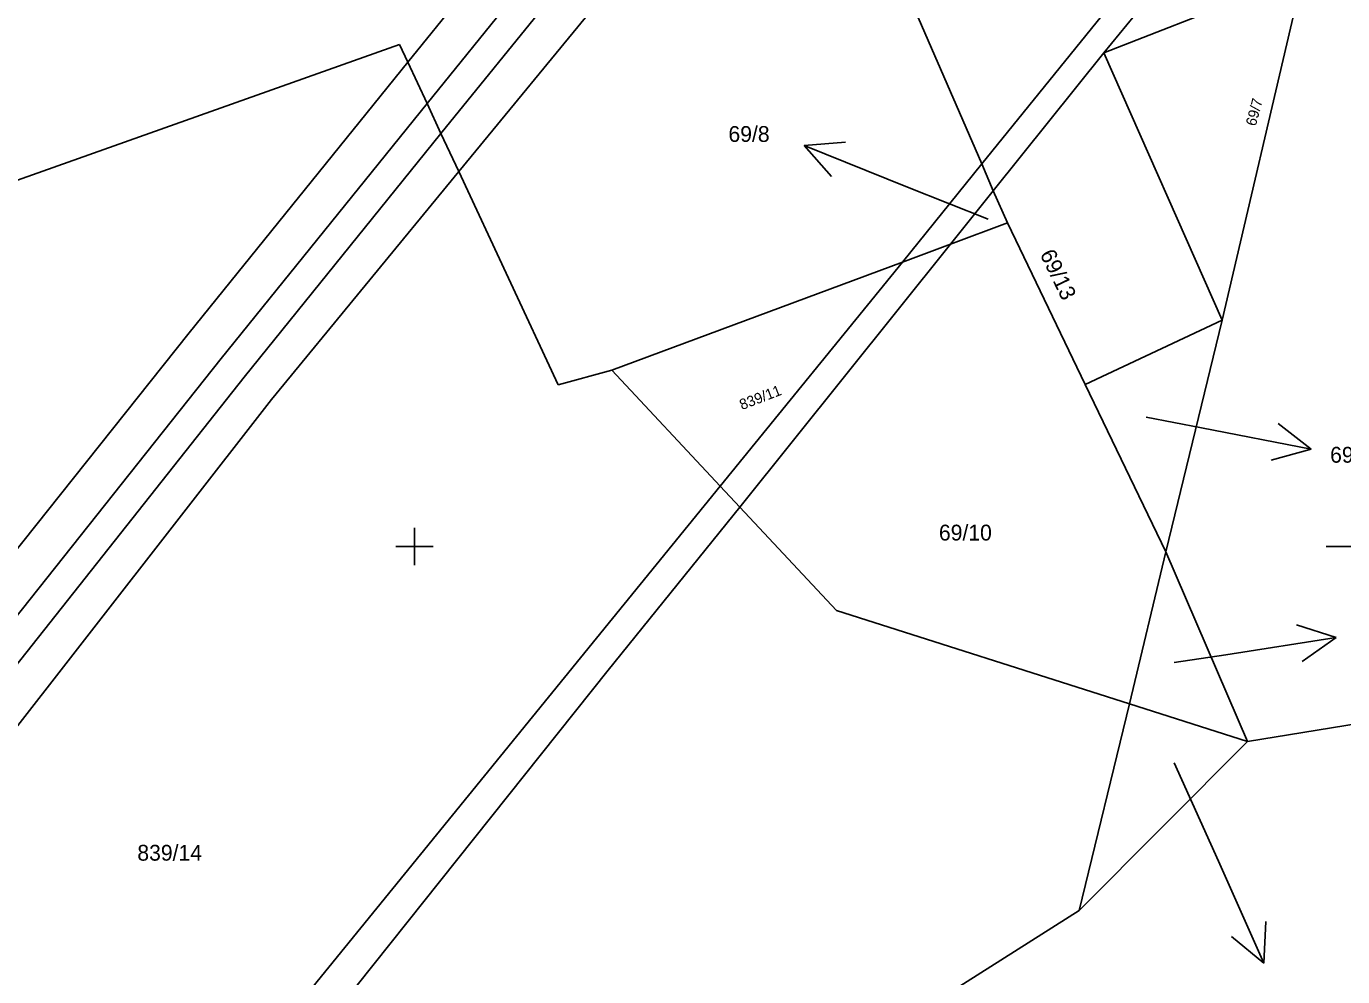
# Model space of a CAD drawing. Extents: x -711081 to -709338, y -1025122 to -1024092.
# Drawn here: x -709810.43 to -709775.06, y -1024586.56 to -1024561.03 of the extents above; entities that cross this region are included whole.
import ezdxf

# ---------------------------------------------------------------- set-up
doc = ezdxf.new("R2010")
doc.units = 0
for name, color, linetype in [('Z_hektometricka_sit', 7, 'Continuous'), ('Z_katastr_cisla_pozemkova', 7, 'Continuous'), ('Z_katastr_hranice', 7, 'Continuous'), ('Z_katastr_parcelni_cislo_odkaz', 7, 'Continuous'), ('Z_katastr_vnitrni_kresba', 7, 'Continuous')]:
    doc.layers.add(name, color=color, linetype=linetype)

msp = doc.modelspace()

# ---------------------------------------------------------------- linework, layer by layer
at = {"layer": 'Z_hektometricka_sit'}
for p, q in [((-709800, -1024574.5), (-709800, -1024575.5)), ((-709800.5, -1024575), (-709799.5, -1024575)), ((-709775.5, -1024575), (-709774.5, -1024575))]:
    msp.add_line(p, q, dxfattribs=at)
at = {"layer": 'Z_katastr_hranice'}
for p, q in [((-709789.55, -1024553.67), (-709784.76, -1024564.72)), ((-709781.48, -1024561.74), (-709775.43, -1024554.39)), ((-709776.13, -1024559.65), (-709781.48, -1024561.74)), ((-709776.13, -1024559.65), (-709778.3, -1024568.92)), ((-709800.4, -1024561.52), (-709817.08, -1024567.43)), ((-709800.18, -1024561.99), (-709800.4, -1024561.52)), ((-709784.45, -1024565.45), (-709781.48, -1024561.74)), ((-709781.48, -1024561.74), (-709778.3, -1024568.92)), ((-709799.66, -1024563.1), (-709800.18, -1024561.99)), ((-709799.29, -1024563.91), (-709799.66, -1024563.1)), ((-709798.81, -1024564.93), (-709799.29, -1024563.91)), ((-709784.76, -1024564.72), (-709784.45, -1024565.45)), ((-709796.14, -1024570.66), (-709798.81, -1024564.93)), ((-709785.6, -1024566.88), (-709784.45, -1024565.45)), ((-709784.07, -1024566.31), (-709784.45, -1024565.45)), ((-709785.6, -1024566.88), (-709784.07, -1024566.31)), ((-709781.98, -1024570.65), (-709784.07, -1024566.31)), ((-709791.26, -1024573.94), (-709785.6, -1024566.88)), ((-709785.6, -1024566.88), (-709786.89, -1024567.36)), ((-709786.89, -1024567.36), (-709794.7, -1024570.26)), ((-709778.3, -1024568.92), (-709781.98, -1024570.65)), ((-709778.3, -1024568.92), (-709779.81, -1024575.14)), ((-709794.7, -1024570.26), (-709796.14, -1024570.66)), ((-709794.7, -1024570.26), (-709791.79, -1024573.38)), ((-709781.98, -1024570.65), (-709779.81, -1024575.14)), ((-709791.79, -1024573.38), (-709791.26, -1024573.94)), ((-709794.8, -1024578.32), (-709791.26, -1024573.94)), ((-709791.26, -1024573.94), (-709788.66, -1024576.72)), ((-709779.81, -1024575.14), (-709780.79, -1024579.23)), ((-709779.81, -1024575.14), (-709777.62, -1024580.24)), ((-709788.66, -1024576.72), (-709780.79, -1024579.23)), ((-709813.14, -1024601.32), (-709794.8, -1024578.32)), ((-709777.62, -1024580.24), (-709765.84, -1024578.33)), ((-709780.79, -1024579.23), (-709782.14, -1024584.78)), ((-709780.79, -1024579.23), (-709777.62, -1024580.24)), ((-709777.62, -1024580.24), (-709782.14, -1024584.78)), ((-709782.14, -1024584.78), (-709785.52, -1024586.92))]:
    msp.add_line(p, q, dxfattribs=at)
at = {"layer": 'Z_katastr_parcelni_cislo_odkaz'}
for p, q in [((-709789.532, -1024564.226), (-709788.416, -1024564.137)), ((-709786.75, -1024565.35), (-709789.532, -1024564.226)), ((-709789.532, -1024564.226), (-709788.792, -1024565.065)), ((-709784.59, -1024566.21), (-709786.75, -1024565.35)), ((-709780.34, -1024571.53), (-709778.85, -1024571.81)), ((-709778.85, -1024571.81), (-709775.904, -1024572.383)), ((-709775.904, -1024572.383), (-709776.792, -1024571.7)), ((-709775.904, -1024572.383), (-709776.983, -1024572.683)), ((-709775.236, -1024577.441), (-709776.303, -1024577.103)), ((-709778.2, -1024577.91), (-709775.236, -1024577.441)), ((-709775.236, -1024577.441), (-709776.147, -1024578.092)), ((-709779.59, -1024578.12), (-709778.2, -1024577.91)), ((-709779.59, -1024580.81), (-709778.4, -1024583.45)), ((-709778.4, -1024583.45), (-709777.179, -1024586.192)), ((-709777.179, -1024586.192), (-709777.129, -1024585.073)), ((-709777.179, -1024586.192), (-709778.044, -1024585.48))]:
    msp.add_line(p, q, dxfattribs=at)
at = {"layer": 'Z_katastr_vnitrni_kresba'}
for p, q in [((-709800.18, -1024561.99), (-709790.91, -1024550.54)), ((-709790.42, -1024551.68), (-709799.66, -1024563.1)), ((-709799.29, -1024563.91), (-709790.06, -1024552.5)), ((-709789.55, -1024553.67), (-709798.81, -1024564.93)), ((-709784.76, -1024564.72), (-709775.75, -1024553.6)), ((-709806.06, -1024569.26), (-709800.18, -1024561.99)), ((-709799.66, -1024563.1), (-709805.2, -1024569.95)), ((-709804.58, -1024570.45), (-709799.29, -1024563.91)), ((-709786.89, -1024567.36), (-709784.76, -1024564.72)), ((-709798.81, -1024564.93), (-709803.84, -1024571.05)), ((-709791.79, -1024573.38), (-709786.89, -1024567.36)), ((-709824.44, -1024592.34), (-709806.06, -1024569.26)), ((-709805.2, -1024569.95), (-709823.55, -1024593.05)), ((-709822.88, -1024593.58), (-709804.58, -1024570.45)), ((-709803.84, -1024571.05), (-709821.96, -1024594.31)), ((-709813.99, -1024600.65), (-709791.79, -1024573.38))]:
    msp.add_line(p, q, dxfattribs=at)

# ---------------------------------------------------------------- texts
at = {"layer": 'Z_katastr_cisla_pozemkova'}
for s, height, rotation, p in [('69/7', 0.285, 75, (-709777.396, -1024563.726)), ('69/13', 0.425, 296, (-709783.206, -1024567.147)), ('839/11', 0.285, 21, (-709791.203, -1024571.338))]:
    msp.add_text(s, height=height, rotation=rotation, dxfattribs=at).set_placement(p)
for s, p in [('69/8', (-709791.565, -1024564.133)), ('69/9', (-709775.397, -1024572.75)), ('69/10', (-709785.909, -1024574.84)), ('839/14', (-709807.449, -1024583.44))]:
    msp.add_text(s, height=0.425, dxfattribs=at).set_placement(p)

doc.saveas('drawing.dxf')
